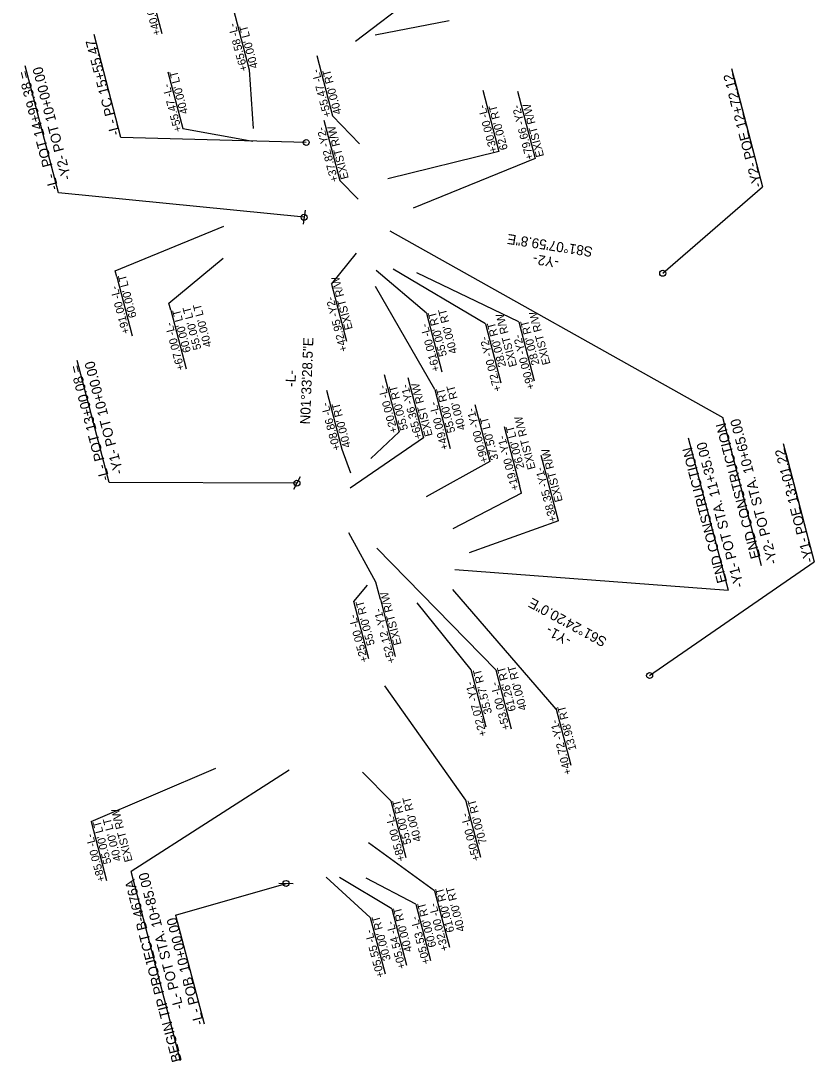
# Model space of a CAD drawing. Extents: x 1366624 to 1367908, y 878728 to 880804.
# Drawn here: x 1367313 to 1367908, y 878728 to 879509 of the extents above; entities that cross this region are included whole.
import ezdxf

# ---------------------------------------------------------------- set-up
doc = ezdxf.new("R2010")
doc.units = 0
for name, color, linetype in [('HNTB LOGO CELL', 7, 'Continuous'), ('HNTB Spark', 7, 'Continuous'), ('Old_Level_23', 7, 'Continuous'), ('Sheet Clip Boundary CELL', 7, 'Continuous'), ('Sheet Plan And Profile CELL', 7, 'Continuous'), ('Sheet Plot Border Inside CELL', 7, 'Continuous'), ('Sheet Plot Border Outside CELL', 7, 'Continuous'), ('Sheet Sticker Incomplete CELL', 7, 'Continuous')]:
    doc.layers.add(name, color=color, linetype=linetype)

msp = doc.modelspace()

# ---------------------------------------------------------------- linework, layer by layer
at = {"layer": 'HNTB LOGO CELL'}
for p, q in [((1367526.71, 879366.78), (1367525.07, 879356.28)), ((1367523.02, 879166.97), (1367517.94, 879157.64)), ((1367506.97, 878862.45), (1367517.59, 878862.16))]:
    msp.add_line(p, q, dxfattribs=at)
at = {"layer": 'HNTB Spark'}
for p, q in [((1367686.92, 879283.09), (1367698.46, 879239.08)), ((1367661.92, 879281.57), (1367673.46, 879237.55)), ((1367542.66, 879231.85), (1367554.19, 879187.83)), ((1367675.81, 879204.65), (1367687.34, 879160.64)), ((1367688.85, 879154.88), (1367687.34, 879160.64)), ((1367688.85, 879154.88), (1367637.4, 879128.15)), ((1367669.71, 879022.31), (1367580.42, 879113.55)), ((1367669.71, 879022.31), (1367681.25, 878978.29)), ((1367623.7, 878856.85), (1367574.16, 878892.64)), ((1367609.66, 878846.85), (1367572.44, 878866.21)), ((1367623.7, 878856.85), (1367634.8, 878814.5)), ((1367609.66, 878846.85), (1367620.76, 878804.5))]:
    msp.add_line(p, q, dxfattribs=at)
for points in [[(1367661.92, 879281.57), (1367592.71, 879322.74)], [(1367686.92, 879283.09), (1367610.49, 879319.96)], [(1367554.19, 879187.83), (1367560.69, 879169.96)]]:
    msp.add_lwpolyline(points, dxfattribs=at)
at = {"layer": 'Old_Level_23'}
for p, q in [((1367388.52, 879421.35), (1367368.32, 879498.41)), ((1367341.56, 879379.74), (1367316.62, 879474.89)), ((1367846.47, 879473.12), (1367869.74, 879384.34)), ((1367846.47, 879473.12), (1367869.74, 879384.34)), ((1367848.39, 879465.81), (1367869.74, 879384.34)), ((1367848.39, 879465.81), (1367869.74, 879384.34)), ((1367527.41, 879417.57), (1367388.52, 879421.35)), ((1367794.76, 879319.56), (1367869.74, 879384.34)), ((1367525.89, 879361.5), (1367341.56, 879379.74)), ((1367590.11, 879351.48), (1367839.77, 879211.55)), ((1367379.6, 879162.81), (1367355.62, 879254.31)), ((1367868.9, 879100.41), (1367839.77, 879211.55)), ((1367813.85, 879196.29), (1367843.77, 879082.15)), ((1367885.12, 879192), (1367908.39, 879103.21)), ((1367887.04, 879184.69), (1367908.39, 879103.21)), ((1367520.47, 879162.28), (1367379.6, 879162.81)), ((1367639, 879097.67), (1367843.77, 879082.15)), ((1367784.94, 879018.11), (1367908.39, 879103.21)), ((1367514.62, 878947.28), (1367396.07, 878871.21)), ((1367433.25, 878729.32), (1367396.07, 878871.21)), ((1367429.46, 878838.66), (1367512.31, 878862.31)), ((1367429.46, 878838.66), (1367450.81, 878757.18))]:
    msp.add_line(p, q, dxfattribs=at)
for centre in [(1367527.41, 879417.57), (1367525.89, 879361.5), (1367794.76, 879319.56), (1367520.47, 879162.28), (1367784.94, 879018.11), (1367512.31, 878862.31), (1367512.31, 878862.31), (1367512.31, 878862.31), (1367512.31, 878862.31), (1367512.31, 878862.31), (1367512.31, 878862.31), (1367512.31, 878862.31)]:
    msp.add_circle(centre, 2.25, dxfattribs=at)
at = {"layer": 'Sheet Clip Boundary CELL'}
for p, q in [((1367419.4, 879499.07), (1367407.79, 879543.38)), ((1367384.25, 879321.37), (1367465.68, 879354.76)), ((1367424.37, 879297.23), (1367465.03, 879330.77)), ((1367385.44, 879316.81), (1367384.25, 879321.37)), ((1367385.44, 879316.81), (1367396.98, 879272.79)), ((1367425.78, 879291.86), (1367424.37, 879297.23)), ((1367425.78, 879291.86), (1367437.31, 879247.84))]:
    msp.add_line(p, q, dxfattribs=at)
at = {"layer": 'Sheet Plot Border Inside CELL'}
for p, q in [((1367472.62, 879517.89), (1367484.63, 879472.04)), ((1367535.39, 879482.82), (1367547.25, 879437.59)), ((1367423.68, 879470.58), (1367434.85, 879427.94)), ((1367484.63, 879472.04), (1367487.59, 879428.03)), ((1367540.74, 879434.33), (1367552.6, 879389.09)), ((1367547.25, 879437.59), (1367567.4, 879416.48)), ((1367552.6, 879389.09), (1367566.27, 879374.99)), ((1367546.41, 879311.36), (1367557.58, 879268.73)), ((1367603.66, 879241.57), (1367615.51, 879196.34)), ((1367579.65, 879087.98), (1367559.47, 879124.93)), ((1367583.04, 879075.07), (1367579.65, 879087.98)), ((1367583.04, 879075.07), (1367594.21, 879032.43)), ((1367366.12, 878908.68), (1367377.69, 878864.55)), ((1367575.47, 878836.82), (1367542.45, 878867.04)), ((1367591.52, 878843.3), (1367552.44, 878866.76)), ((1367591.52, 878843.3), (1367602.62, 878800.95)), ((1367575.47, 878836.82), (1367586.57, 878794.46))]:
    msp.add_line(p, q, dxfattribs=at)
for points in [[(1367609.06, 879527.55), (1367564.49, 879493.17)], [(1367434.85, 879427.94), (1367487.43, 879418.66)], [(1367546.41, 879311.36), (1367565.17, 879334.65)], [(1367615.51, 879196.34), (1367560.38, 879158.57)], [(1367366.12, 878908.68), (1367459.64, 878948.77)]]:
    msp.add_lwpolyline(points, dxfattribs=at)
at = {"layer": 'Sheet Plot Border Outside CELL'}
for p, q in [((1367617.55, 879289.6), (1367629.09, 879245.59)), ((1367623.82, 879232.36), (1367635.35, 879188.34))]:
    msp.add_line(p, q, dxfattribs=at)
for points in [[(1367617.55, 879289.6), (1367579.82, 879321.64)], [(1367623.82, 879232.36), (1367579.5, 879309.65)]]:
    msp.add_lwpolyline(points, dxfattribs=at)
at = {"layer": 'Sheet Sticker Incomplete CELL'}
for p, q in [((1367634.56, 879508.74), (1367579.07, 879497.93)), ((1367659.89, 879456.89), (1367671.97, 879410.81)), ((1367685.92, 879455.94), (1367699.13, 879405.53)), ((1367671.97, 879410.81), (1367588.7, 879390.43)), ((1367699.13, 879405.53), (1367607.57, 879368.3)), ((1367585.91, 879243.68), (1367597.16, 879200.77)), ((1367653.8, 879221.31), (1367665.04, 879178.4)), ((1367716.52, 879134.08), (1367703.72, 879182.89)), ((1367716.52, 879134.08), (1367649.61, 879110.12)), ((1367563.24, 879073.61), (1367573.41, 879085.73)), ((1367714.99, 878992.98), (1367637.33, 879082.65)), ((1367574.49, 879030.69), (1367563.24, 879073.61)), ((1367651.19, 879022.27), (1367610.63, 879072.62)), ((1367662.44, 878979.35), (1367651.19, 879022.27)), ((1367726.09, 878950.64), (1367714.85, 878993.55)), ((1367590.99, 878924.21), (1367569.6, 878945.78)), ((1367590.99, 878924.21), (1367602.09, 878881.86)), ((1367658.49, 878881.81), (1367647.25, 878924.73))]:
    msp.add_line(p, q, dxfattribs=at)
for points in [[(1367597.16, 879200.77), (1367575.99, 879180.69)], [(1367665.04, 879178.4), (1367617.44, 879152.13)], [(1367647.25, 878924.73), (1367586.36, 879010.35)]]:
    msp.add_lwpolyline(points, dxfattribs=at)

# ---------------------------------------------------------------- texts
at = {"layer": 'HNTB Spark'}
for s, p in [('EXIST R/W', (1367685.63, 879250.26)), ("28.00' RT", (1367702.44, 879251.49)), ('EXIST R/W', (1367710.63, 879251.78)), ("28.00' RT", (1367677.44, 879249.97)), ('+72.00 -Y2-', (1367673.94, 879231.78)), ('+90.00 -Y2-', (1367698.93, 879233.3)), ('+08.86 -L-', (1367553.22, 879187.58)), ("40.00' RT", (1367560.96, 879189.61)), ('EXIST R/W', (1367699.52, 879173.34)), ('+19.00 -Y1-', (1367687.09, 879157.64)), ("26.00' LT", (1367691.14, 879173.74)), ("61.26' RT", (1367684.87, 878992.1)), ("40.00' RT", (1367692.97, 878992.74)), ('+53.00 -L-', (1367680.28, 878978.04)), ("61.00' RT", (1367638.63, 878826.42)), ("40.00' RT", (1367646.6, 878827.02)), ("60.00' RT", (1367625.14, 878815.24)), ('+32.00 -L-', (1367634.18, 878812.4)), ('+05.53 -L-', (1367620.32, 878802.6))]:
    msp.add_text(s, height=6, rotation=104.68512, dxfattribs=at).set_placement(p)
at = {"layer": 'Old_Level_23'}
for s, p in [('-L- PC 15+55.47', (1367387.85, 879423.87)), ('-L-  POT 14+99.38 =', (1367341.76, 879382.95)), ('-Y2- POT 10+00.00', (1367351.41, 879390.51)), ('-Y2- POE 12+72.12', (1367869.58, 879384.93)), ('-Y1- POT 10+00.00', (1367390.41, 879169.93)), ('-L- POT 13+00.08 =', (1367380.02, 879165.19)), ('END CONSTRUCTION', (1367868.28, 879106.75)), ('-Y2- POT STA. 10+65.00', (1367881, 879102.58)), ('-Y1- POT STA. 11+35.00', (1367855.67, 879085.07)), ('END CONSTRUCTION', (1367843.14, 879088.5)), ('-Y1- POE 13+01.22', (1367908.24, 879103.81)), ('-L- POT STA. 10+85.00', (1367435.53, 878769)), ('BEGIN TIP PROJECT B-4676A', (1367434.25, 878729.48)), ('10+00.00', (1367440.48, 878796.6)), ('POB', (1367446.83, 878772.38)), ('- ', (1367448.45, 878766.19)), ('L', (1367449.93, 878760.56)), ('-', (1367450.81, 878757.18))]:
    msp.add_text(s, height=7.5, rotation=104.68512, dxfattribs=at).set_placement(p)
at = {"layer": 'Sheet Clip Boundary CELL'}
for s, p in [('+40.00 -L-', (1367418.5, 879498.57)), ("60.00' LT", (1367400.35, 879286.95)), ('+91.00 -L-', (1367395.21, 879274.98)), ("60.00' LT", (1367441.11, 879260.95)), ("55.00' LT", (1367448.85, 879262.98)), ("40.00' LT", (1367456.59, 879265)), ('+67.00 -L-', (1367436.34, 879247.59))]:
    msp.add_text(s, height=6, rotation=104.68512, dxfattribs=at).set_placement(p)
at = {"layer": 'Sheet Plan And Profile CELL'}
for s, rotation, p in [('S81°07\'59.8"E', 171.13327, (1367742.72, 879339.1)), ('-', 171.13327, (1367701.27, 879333.42)), ('Y2', 171.13327, (1367713.93, 879331.45)), ('-', 171.13327, (1367717.37, 879330.91)), ('N01°33\'28.5"E', 87.73594, (1367530.27, 879206.21)), ('-', 87.73594, (1367519.73, 879243.53)), ('L', 87.73594, (1367519.5, 879237.71)), ('-', 87.73594, (1367519.37, 879234.23)), ('S61°24\'20.0"E', 151.40557, (1367753.56, 879045.67)), ('-', 151.40557, (1367712.63, 879054.32)), ('Y1', 151.40557, (1367723.88, 879048.19)), ('-', 151.40557, (1367726.94, 879046.52))]:
    msp.add_text(s, height=7.5, rotation=rotation, dxfattribs=at).set_placement(p)
at = {"layer": 'Sheet Plot Border Inside CELL'}
for s, p in [('+65.58 -L-', (1367483.66, 879471.79)), ("40.00' LT", (1367491.4, 879473.82)), ("40.00' LT", (1367438.95, 879439.65)), ('+55.47 -L-', (1367546.28, 879437.34)), ("40.00' RT", (1367554.02, 879439.36)), ('+55.47 -L-', (1367434.31, 879426.33)), ('+37.82 -Y2-', (1367551.63, 879388.84)), ('EXIST R/W', (1367559.37, 879390.87)), ('EXIST R/W', (1367562.32, 879278.01)), ('+42.95 -Y2-', (1367558.49, 879261.59)), ('+65.36 -Y1-', (1367614.54, 879196.09)), ('EXIST R/W', (1367622.28, 879198.12)), ('EXIST R/W', (1367598.95, 879041.71)), ('+52.12 -Y1-', (1367594.39, 879028.07)), ('EXIST R/W', (1367397.26, 878879.26)), ("55.00' LT", (1367381.41, 878877.69)), ("40.00' LT", (1367389.02, 878879.69)), ('+85.00 -L-', (1367376.77, 878864.37)), ("40.00' RT", (1367607, 878811.69)), ("30.00' RT", (1367590.95, 878805.2)), ('+05.54 -L-', (1367602.18, 878799.05)), ('+05.55 -L-', (1367586.13, 878792.57))]:
    msp.add_text(s, height=6, rotation=104.68512, dxfattribs=at).set_placement(p)
at = {"layer": 'Sheet Plot Border Outside CELL'}
for s, p in [("40.00' RT", (1367640.81, 879260.03)), ("55.00' RT", (1367633.07, 879258)), ('+61.00 -L-', (1367627.76, 879246.72)), ("55.00' RT", (1367639.33, 879200.76)), ("40.00' RT", (1367647.07, 879202.78)), ('+49.00 -L-', (1367634.38, 879188.09))]:
    msp.add_text(s, height=6, rotation=104.68512, dxfattribs=at).set_placement(p)
at = {"layer": 'Sheet Sticker Incomplete CELL'}
for s, p in [('+30.00 -L-', (1367670.96, 879410.71)), ("62.00' RT", (1367678.7, 879412.73)), ('+79.66 -Y2-', (1367698.12, 879405.42)), ('EXIST R/W', (1367705.86, 879407.45)), ('+20.00 -L-', (1367596.15, 879200.66)), ("55.00' RT", (1367603.89, 879202.69)), ('+90.00 -Y1-', (1367664.04, 879178.29)), ("37.50' LT", (1367671.78, 879180.32)), ('EXIST R/W', (1367719.85, 879148.98)), ('+38.35 -Y1-', (1367715.52, 879133.92)), ("55.00' RT", (1367578.91, 879041.44)), ('+25.00 -L-', (1367573.96, 879028.77)), ("35.57' RT", (1367666.86, 878990.1)), ('+22.07 -Y1-', (1367662.99, 878973.3)), ("13.98' RT", (1367730.15, 878962.77)), ('+40.72 -Y1-', (1367726.65, 878944.58)), ("55.00' RT", (1367606.41, 878892.31)), ("40.00' RT", (1367614.02, 878894.31)), ("70.00' RT", (1367662.91, 878892.56)), ('+85.00 -L-', (1367601.59, 878879.68)), ('+50.00 -L-', (1367657.96, 878879.89))]:
    msp.add_text(s, height=6, rotation=104.68512, dxfattribs=at).set_placement(p)

doc.saveas('drawing.dxf')
